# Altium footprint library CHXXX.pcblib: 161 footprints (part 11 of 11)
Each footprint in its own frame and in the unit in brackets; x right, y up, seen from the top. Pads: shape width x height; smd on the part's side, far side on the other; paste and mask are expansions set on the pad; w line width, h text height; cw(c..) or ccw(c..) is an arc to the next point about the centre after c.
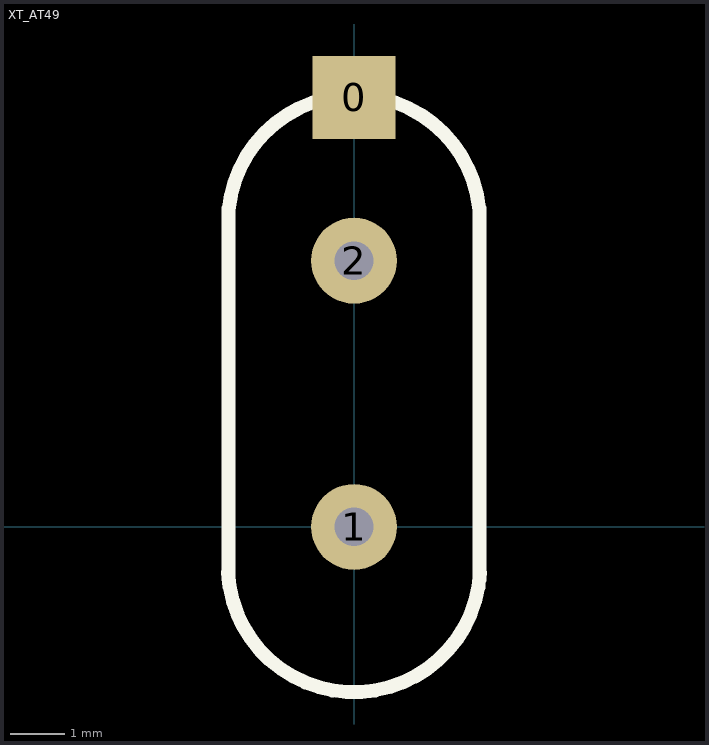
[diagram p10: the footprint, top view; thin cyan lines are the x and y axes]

## XT_AT49 [mil]
pads (3):
  rect 60x60 smd: 0(0,310)
  round 62 hole 28: 1(0,0) 2(0,192.13)
TopOverlay:
  lines w10: -90.88,-33.02 ccw(c0,-28.35) 90.87,-33.26 ; -90.55,-37.8 -90.55,229.92 ; -90.4,229.22 cw(c0,220.47) 90.4,229.17 ; 90.55,-38 90.55,229.92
